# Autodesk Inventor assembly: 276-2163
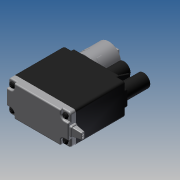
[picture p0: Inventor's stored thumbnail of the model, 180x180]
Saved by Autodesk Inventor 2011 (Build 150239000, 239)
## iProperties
Company: Autodesk Inc.
Created: 2010-06
Part Number: 276-2163
Document SubType Name: Assembly
Designer: Autodesk Inc.
Catalog Web Link: http://www.vexrobotics.com/products/accessories/motion/276-2163.html
Description: Additional motors can be used to provide a robot with additional functionality; more motors means more features.
Vendor: Innovation First, Inc.
Author: Autodesk Inc.
Title: VEX Robotics Kit of Parts
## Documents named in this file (8)
- C:\Data Folder\VEX KOP 2010\VEX Parts Kit\Motion\VEX Motor.iam
- C:\Data Folder\VEX KOP 2010\VEX Parts Kit\Motion\VEX Motor Top.ipt
- C:\Data Folder\VEX KOP 2010\VEX Parts Kit\Motion\VEX Motor Insert.ipt
- C:\Data Folder\VEX KOP 2010\VEX Parts Kit\Motion\VEX Motor Clutch.ipt
- C:\Data Folder\VEX KOP 2010\VEX Parts Kit\Motion\VEX Motor Clutch Axle.ipt
- C:\Data Folder\VEX KOP 2010\VEX Parts Kit\Motion\VEX Motor Bottom.ipt
- C:\Data Folder\VEX KOP 2010\VEX Parts Kit\Motion\ANSI B18.6.3 - 1-64 UNC - 0.1875(4A).ipt
- C:\Data Folder\VEX KOP 2010\VEX Parts Kit\Motion\VEX Motor Wire Support.ipt
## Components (15 placed, 7 different names)
1. VEX Motor Top:1 — Insert:1, Insert:2, Insert:3, Angle:1, Flush:2, Insert:5
2. VEX Motor Insert:1 — Insert:1
3. VEX Motor Insert:2 — Insert:2
4. VEX Motor Clutch:1 — Insert:3, Angle:1, Mate:1, Mate:2, Flush:1
5. VEX Motor Clutch Axle:1 — Mate:1, Mate:2, Flush:1
6. VEX Motor Bottom:1 — Flush:2, Insert:4, Mate:3, Angle:2, Mate:6, Angle:3, Flush:3
7. VEX Motor Wire Support:1 — Mate:4, Mate:6, Angle:3, Flush:3
8. Cross Recessed Pan Head Machine Screw - Type I - Inch No. 1 - 64 - 3/16:1 — Insert:4
9. Cross Recessed Pan Head Machine Screw - Type I - Inch No. 1 - 64 - 3/16:2
10. Cross Recessed Pan Head Machine Screw - Type I - Inch No. 1 - 64 - 3/16:3
11. Cross Recessed Pan Head Machine Screw - Type I - Inch No. 1 - 64 - 3/16:4
12. Cross Recessed Pan Head Machine Screw - Type I - Inch No. 1 - 64 - 3/16:5 — Insert:5
13. Cross Recessed Pan Head Machine Screw - Type I - Inch No. 1 - 64 - 3/16:6
14. Cross Recessed Pan Head Machine Screw - Type I - Inch No. 1 - 64 - 3/16:7
15. Cross Recessed Pan Head Machine Screw - Type I - Inch No. 1 - 64 - 3/16:8
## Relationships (16: Insert 5, Mate 5, Angle 3, Flush 3)
- Insert:1: VEX Motor Top:1 ↔ VEX Motor Insert:1
- Insert:2: VEX Motor Top:1 ↔ VEX Motor Insert:2
- Insert:3: VEX Motor Top:1 ↔ VEX Motor Clutch:1
- Angle:1: VEX Motor Top:1 ↔ VEX Motor Clutch:1
- Mate:1: VEX Motor Clutch:1 ↔ VEX Motor Clutch Axle:1
- Mate:2: VEX Motor Clutch:1 ↔ VEX Motor Clutch Axle:1
- Flush:1: VEX Motor Clutch:1 ↔ VEX Motor Clutch Axle:1
- Flush:2: VEX Motor Top:1 ↔ VEX Motor Bottom:1
- Insert:4: VEX Motor Bottom:1 ↔ Cross Recessed Pan Head Machine Screw - Type I - Inch No. 1 - 64 - 3/16:1
- Insert:5: VEX Motor Top:1 ↔ Cross Recessed Pan Head Machine Screw - Type I - Inch No. 1 - 64 - 3/16:5
- Mate:3: VEX Motor Bottom:1
- Angle:2: VEX Motor Bottom:1
- Mate:4: VEX Motor Wire Support:1
- Mate:6: VEX Motor Bottom:1 ↔ VEX Motor Wire Support:1
- Angle:3: VEX Motor Bottom:1 ↔ VEX Motor Wire Support:1
- Flush:3: VEX Motor Bottom:1 ↔ VEX Motor Wire Support:1
